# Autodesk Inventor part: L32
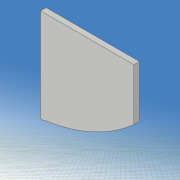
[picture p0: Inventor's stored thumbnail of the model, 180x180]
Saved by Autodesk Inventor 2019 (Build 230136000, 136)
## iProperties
Created: 2021-05
Part Number: L32
Material: 一般
Document SubType Name: Modeling
Designer: kikut
Density: 1 g/cm^3
Appearance: 既定
Mass: 0.00934248 g
Surface Area: 0.426451 cm^2
Volume: 0.00934248 cm^3
Author: kikut
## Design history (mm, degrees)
sketch "スケッチ1"
  geometry: L1 (80, 60)-(-80, 60); L2 (-80, 60)-(-80, -60); L3 (-80, -60)-(80, -60); L4 (80, -60)-(80, 60); L5 (80, 60)-(-80, -60); L6 (-80, 60)-(80, -60); 1 further point
  constraints: 12 end point, 2 midpoint, 2 parallel, 1 horizontal, 1 perpendicular
  dimensions: "d0" = 160 distance of L2.end L3.end; "d1" = 120 distance of L1.end L2.end
extrude "押し出し1" new body sketch "スケッチ1" stored distance "d2" = 0.6; taper "d3" = 0 deg
sketch "スケッチ2"
  geometry: L1 (-140, 0)-(140, 0) reference; L2 (0, -54)-(20, -30); L3 (0, 54)-(20, 30); L4 (0, -3)-(6.514, -3); L5 (6.514, -3)-(16, -6); L6 (16, -6)-(24, -3); L7 (24, -3)-(33.716, -3); L8 (0, 3)-(6.514, 3); L9 (6.514, 3)-(16, 6); L10 (16, 6)-(24, 3); L11 (24, 3)-(33.716, 3); L12 (0, -98)-(0, 98) reference; L13 (-100, -70)-(100, -70); L14 (100, -70)-(100, 70); L15 (100, 70)-(-100, 70); L16 (-100, 70)-(-100, -70); L17 (-100, -70)-(100, 70); L18 (100, -70)-(-100, 70); A1 r 60 centre (54.312, 28.5) between (0, 54) and (0, 3); A2 r 60 centre (54.312, -28.5) between (0, -3) and (0, -54); A3 r 18.111 centre (18, -12) between (20, -30) and (33.716, -3); A4 r 18.111 centre (18, 12) between (33.716, 3) and (20, 30); 1 further point
  constraints: 32 end point, 8 point on circle, 8 symmetric about line, 4 centre point, 3 horizontal, 2 collinear, 2 midpoint, 2 parallel, 1 perpendicular
  dimensions: "d5" = 60 radius of A1; "d6" = 6 distance of L8.start L4.start; "d7" = 108 distance of L3.start L2.start; "d8" = 0 horizontal distance of L3.start L8.start; "d9" = 60 distance of L3.end L2.end; "d10" = 0 horizontal distance of point (0, 0) L3.start; "d11" = 20 horizontal distance of L3.start L3.end; "d12" = 24 distance of A4.centre A3.centre; "d13" = 6 distance of L11.end L7.end; "d14" = 12 distance of L9.end L5.end; "d15" = 16 distance from line of L12 L5.end; "d16" = 24 distance from line of L6.end L12; "d17" = 200 distance of L14.end L15.end; "d18" = 140 distance of L15.end L13.start; "d30" = 18 distance from line of L12 A4.centre
extrude "押し出し2" cut sketch "スケッチ2" stored distance "d19" = 10; taper "d20" = 0 deg
sketch "スケッチ3"
  geometry: L1 (49.705, -17.97)-(33.948, -15.191); L2 (33.948, -15.191)-(34.295, -13.222); L3 (34.295, -13.222)-(50.052, -16); L4 (50.052, -16)-(49.705, -17.97); L5 (49.705, -17.97)-(34.295, -13.222); L6 (33.948, -15.191)-(50.052, -16); L7 (50.052, 16)-(34.295, 13.222); L8 (34.295, 13.222)-(33.948, 15.191); L9 (33.948, 15.191)-(49.705, 17.97); L10 (49.705, 17.97)-(50.052, 16); L11 (50.052, 16)-(33.948, 15.191); L12 (34.295, 13.222)-(49.705, 17.97); L13 (-112, 0)-(112, 0) reference; L14 (0, -84)-(0, 84) reference; 3 further points
  constraints: 24 end point, 4 midpoint, 4 parallel, 2 perpendicular, 2 symmetric about line
  dimensions: "d21" = 2 distance of L3.end L1.start; "d22" = 2 distance of L9.end L7.start; "d23" = 16 distance of L8.end L9.end; "d24" = 42 distance from line of L14 point (42, 15.596); "d26" = 10 deg angle of L7 L13; "d62" = 16 distance from line of L3.end L13
extrude "押し出し3" join sketch "スケッチ3" distance "d27" = 0.6; taper "d28" = 0 deg
fillet "フィレット1" dims "d31" = 2
fillet "フィレット2" dims "d32" = 1
sketch "スケッチ7"
  geometry: L1 (-20, 60)-(80, 60); L2 (80, 60)-(80, -60); L3 (80, -60)-(-20, -60); L4 (-20, -60)-(-20, 60); L5 (0, -82.207)-(0, 85.793) reference; L6 (-40, 0)-(100, 0) reference; L7 (20, -20)-(30, -20); L8 (30, -20)-(30, -30); L9 (30, -30)-(20, -30); L10 (20, -30)-(20, -20); 1 further point
  constraints: 16 end point, 4 parallel, 2 horizontal, 2 perpendicular, 1 other
  dimensions: "d80" = 120 distance of L3.end L1.start; "d81" = 20 distance between parallel lines of L5 L4; "d82" = 100 distance of L1.start L1.end; "d84" = 10 distance of L8.end L9.end; "d85" = 10 distance of L7.end L8.end; "d86" = 40 distance between parallel lines of L4 L10; "d93" = 30 distance between parallel lines of L3 L9
extrude "押し出し5" cut sketch "スケッチ7" stored distance "d87" = 10; taper "d88" = 0 deg
node "ソリッド1"
